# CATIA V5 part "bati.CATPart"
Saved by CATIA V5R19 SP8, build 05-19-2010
Part number: bati
Bounding box of the stored display mesh (mm): x -23.97 to 210.736, y -159.271 to 25, z -43 to 0
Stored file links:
  F:\CFAO\Hberriche\bati.CATPart
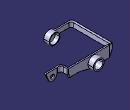
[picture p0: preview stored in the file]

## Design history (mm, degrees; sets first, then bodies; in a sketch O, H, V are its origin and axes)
Body1 (main body)
  Sketch1 on zx-plane, origin (0, 0, 0), H (-1, 0, 0), V (0, 0, 1)
    line L1 (-150, -30) -> (-150, 0)
    line L2 (-150, 0) -> (0, 0)
    line L3 (-150, -30) -> (-110, -30)
    line L4 (-110, -30) -> (-70, -40)
    point P5 (-70, -40)
    line L5 (-70, -40) -> (0, -40)
    point P6 (-70, -40)
    line L6 (0, 0) -> (0, -40)
    length L2 = 150
    length L6 = 40
    length L1 = 30
    length L3 = 40
    length L5 = 70
    vertical: L1 V, L6 V
    horizontal: L2 H, L3 H, L5 H
    coincidence: P6 L4, L6 V, P5 P6, L2 H
  Pad1: profile Sketch1, direction (0, 1, 0), length 5
  Sketch2 on xy-plane, origin (0, 0, 0), H (1, 0, 0), V (0, 1, 0)
    line L1 (150, 5) -> (150, -11.5114)
    point P1 (150, 5)
    reference projected line E1 (150, 0) -> (150, 5) from edge [face of Pad1 from Sketch1.L3 | face of Pad1 from Sketch1.L1]
    reference projected line E2 (75, 5) -> (55, 5) from edge [face of Pad1 from Sketch1.L3 | end face of Pad1]
    arc A1 centre (164.4149, -11.5114) radius 14.4149 from (150, -11.5114) to (170.1125, -24.7525) ccw
    line L2 (170.1125, -24.7525) -> (172.4124, -24.7525)
    vertical: L1 V
    coincidence: E1 L1, E2 P1
    tangency: A1 L1
    horizontal: L2 H
  Pad2: profile Sketch2, direction (0, 0, -1), length 20, thin wall 5
  Sketch3 on xy-plane, origin (0, 0, 0), H (1, 0, 0), V (0, 1, 0)
    line L1 (0, 0) -> (-21.8492, -12.1496)
    point P1 (-21.8492, -12.1496)
    line L2 (0, 0) -> (0, 5)
    point P2 (0, 0)
    line L3 (0, 5) -> (-21.8492, -7.1496)
    line L4 (-21.8492, -7.1496) -> (-21.8492, -12.1496)
    point P5 (-21.8492, -12.1496)
    length L2 = 5
    length L1 = 25
    coincidence: P2 L1, P2 H, P5 L1, P1 P5, O P2
    vertical: L2 V, L4 V
    parallelism: L3 L1
  Pad3: profile Sketch3, direction (0, 0, -1), length 40
  Sketch4 on face of Pad3 from Sketch3.L3, origin (-2.1237, 3.8191, 0), H (-0.874, -0.486, 0), V (0, 0, 1)
    line L1 (-2.4299, -40) -> (25, -27.5)
    point P1 (-2.4299, -40)
    line L2 (25, -27.5) -> (25, -40)
    line L3 (25, -40) -> (-2.4299, -40)
    reference projected line E1 (-2.4299, -40) -> (22.5701, -40) from edge [face of Pad3 | face of Pad3 from Sketch3.L3]
    reference projected line E2 (25, 0) -> (25, -30) from edge [face of Pad3 from Sketch3.L4 | face of Pad3 from Sketch3.L1]
    reference projected line E3 (-2.4299, -30) -> (-2.4299, 0) from edge [face of Pad3 from Sketch3.L3 | face of Pad2]
    line L4 (-2.4299, 0) -> (25, -12.5)
    point P4 (-2.4299, 0)
    point P5 (25, -12.5)
    line L5 (25, -12.5) -> (25, 0)
    point P6 (25, 0)
    line L6 (-2.4299, 0) -> (25, 0)
    point P7 (-2.4299, 0)
    reference projected line E6 (-2.4299, -30) -> (-2.4299, 0) from edge [face of Pad3 from Sketch3.L3 | face of Pad2]
    length L5 = 12.5
    length L2 = 12.5
    vertical: L2 V, L5 V
    horizontal: L3 H, L6 H
    coincidence: E1 L3, E2 L2, E3 P1, P4 H, P5 L2, P6 H, P7 L4, E6 P4, P4 P7
  Pocket1: profile Sketch4, direction (0.486, -0.874, 0), through (limit type 6)
  Plane1: type Offset, RefPlane xy-plane, Offset 20, reversed
  Sketch5 on Plane1, origin (0, 0, -20), H (1, 0, 0), V (0, 1, 0)
    line L1 (-21.8492, -7.1496) -> (-23.9705, -9.271)
    point P1 (-21.8492, -7.1496)
    line L2 (-23.9705, -9.271) -> (-23.9705, -159.271)
    point P3 (-23.9705, -159.271)
    reference projected point E1 (-21.8492, -7.1496) from vertex [face of Pocket1 from Sketch4.L1 | face of Pad3 from Sketch3.L4 | face of Pad3 from Sketch3.L3]
    line L3 (-21.8492, -7.1496) -> (-15.9705, -7.1496)
    line L4 (-15.9705, -7.1496) -> (-15.9705, -154.271)
    point P5 (-15.9705, -154.271)
    line L5 (-15.9705, -154.271) -> (76.0295, -154.271)
    point P6 (-15.9705, -154.271)
    line L6 (-23.9705, -159.271) -> (76.0295, -159.271)
    point P8 (-23.9705, -159.271)
    point P9 (76.0295, -159.271)
    line L7 (76.0295, -154.271) -> (76.0295, -159.271)
    point P10 (76.0295, -159.271)
    reference projected line E2 (-21.8492, -12.1496) -> (-21.8492, -7.1496) from edge [face of Pad3 from Sketch3.L4 | face of Pocket1 from Sketch4.L1]
    distance L5 L6 = 5
    distance L4 L2 = 8
    length L2 = 150
    length L1 = 3
    angle E2 L1 = 45
    length L6 = 100
    vertical: L2 V, L4 V, L7 V
    coincidence: E1 P1, P6 L4, P8 L2, P5 P6, P3 P8, P10 L6, P9 P10
    horizontal: L3 H, L5 H, L6 H
  Pad4: profile Sketch5, direction (0, 0, 1), length 8.5, mirrored extent
  Fillet1: radius 3, on edge [face of Pad2 | face of Pad2]
  Fillet2: radius 3, on edge [start face of Pad1 | face of Pad2]
  Fillet3: radius 8, on edge [face of Pad4 from Sketch5.L6 | face of Pad4 from Sketch5.L2]
  Fillet4: radius 8, on edge [face of Pad4 from Sketch5.L4 | face of Pad4 from Sketch5.L5]
  Fillet5: radius 3, on edge [face of Pad4 from Sketch5.L2 | face of Pad4 from Sketch5.L1]
  Fillet6: radius 3, on edge [face of Pad3 from Sketch3.L3 | face of Pad4 from Sketch5.L1]
  Fillet7: radius 3, on edge [face of Pocket1 from Sketch4.L4 | face of Pad3]
  Fillet8: radius 3, on edge [face of Pad3 | face of Pad1 from Sketch1.L4]
  Fillet9: radius 3, on edge [face of Pad1 from Sketch1.L4 | face of Pad2]
  Sketch6 on face of Pad2, origin (0, -19.7525, 0), H (-1, 0, 0), V (0, 0, 1)
    line L1 (-172.4124, 0) -> (-172.4124, -20)
    point P1 (-172.4124, 0)
    point P2 (-172.4124, -20)
    line L2 (-172.4124, 0) -> (-212.4124, 0)
    line L3 (-212.4124, 0) -> (-200.4068, -27.493)
    arc A1 centre (-187.4124, -20) radius 15 from (-200.4068, -27.493) to (-172.4124, -20) ccw
    point P5 (-187.4124, -20)
    reference projected line E1 (-172.4124, 0) -> (-172.4124, -20) from edge [face of Pad2 | face of Pad2]
    reference projected line E2 (-94.0824, 0) -> (-97.4124, 0) from edge [start face of Pad2 | face of Pad2]
    reference projected line E3 (-94.0824, -20) -> (-97.4124, -20) from edge [face of Pad2 | end face of Pad2]
    radius A1 = 15
    length L3 = 30
    length L2 = 40
    distance P5 L1 = 15
    coincidence: P1 H, E1 L1, E2 L2, E3 P2
    vertical: L1 V
    horizontal: L2 H
  Pad5: profile Sketch6, direction (0, -1, 0), length 5
  Fillet10: radius 3, on edge [face of Pad2 | face of Pad5 from Sketch6.A1]
  Fillet11: radius 3, on edge [face of Pad5 | face of Pad5 from Sketch6.L3]
  Sketch7 on start face of Pad1, origin (0, 0, 0), H (1, 0, 0), V (0, 0, 1)
    circle A1 centre (60, -23) radius 20
    point P1 (60, -23)
    reference projected line E1 (0, -30) -> (0, 0) from edge [face of Pad3 from Sketch3.L3 | face of Pad2]
    reference projected line E2 (0, 0) -> (75, 0) from edge [face of Pad5 | face of Pad2]
    radius A1 = 20
    distance P1 E1 = 60
    distance E2 P1 = 23
  Pad6: profile Sketch7, direction (0, 1, 0), length 25
  Sketch8 on end face of Pad6, origin (0, 25, 0), H (-1, 0, 0), V (0, 0, 1)
    circle A1 centre (-60, -23) radius 15
    reference projected circle E1 centre (-60, -23) radius 20 from edge [end face of Pad6 | face of Pad6 from Sketch7.A1]
    radius A1 = 15
    concentricity: E1 A1
  Pocket2: profile Sketch8, direction (0, -1, 0), through (limit type 6)
  Sketch9 on face of Pad5, origin (0, -19.7525, 0), H (-1, 0, 0), V (0, 0, 1)
    circle A1 centre (-187.4124, -20) radius 7.5
    reference projected arc E1 centre (-187.4124, -20) radius 15 from (-200.4068, -27.493) to (-172.4124, -20) ccw from edge [face of Pad5 from Sketch6.A1 | face of Pad5]
    radius A1 = 7.5
    concentricity: E1 A1
  Pocket3: profile Sketch9, direction (0, -1, 0), through (limit type 6)
  Sketch10 on face of Pad4 from Sketch5.L6, origin (0, -159.271, 0), H (1, 0, 0), V (0, 0, 1)
    circle A1 centre (60, -23) radius 20
    reference projected circle E1 centre (60, -23) radius 20 from edge [face of Pad6 from Sketch7.A1 | face of Pad6]
    radius A1 = 20
    concentricity: E1 A1
  Pad7: profile Sketch10, direction (0, 1, 0), length 20
  Sketch11 on end face of Pad7, origin (0, -139.271, 0), H (-1, 0, 0), V (0, 0, 1)
    circle A1 centre (-60, -23) radius 17.5
    reference projected circle E1 centre (-60, -23) radius 15 from edge [end face of Pad6 | face of Pocket2 from Sketch8.A1]
    radius A1 = 17.5
    concentricity: E1 A1
  Pocket4: profile Sketch11, direction (0, -1, 0), length 15
  Plane2: stored without definition
  Sketch12 on face of Pad2, origin (0, 5, 0), H (-1, 0, 0), V (0, 0, 1)
    point P1 (-60, -23)
    distance P1 V = 60
    distance P1 H = 23
  Plane3: type Tangent, Support face of Pad2, RefPoint Sketch12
